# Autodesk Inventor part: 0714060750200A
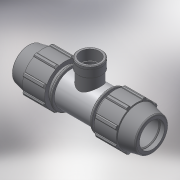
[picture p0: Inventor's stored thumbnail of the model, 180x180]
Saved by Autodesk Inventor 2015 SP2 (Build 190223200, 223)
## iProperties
Created: 2017-02
Part Number: 0714060750200A
Material: Generic
Description: PLASSON TEE WITH THREADED FEMALE OFFTAKE 75-2"-75
Document SubType Name: Modeling
Designer: KIM
Mass: 92.6774 g
Surface Area: 199.44 cm^2
Volume: 66.1981 cm^3
Density: 1 g/cm^3
Appearance: Default
Author: KIM
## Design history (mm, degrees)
derived "87140.ipt"
feature "Solid1::87140.ipt"
feature "Solid2::87140.ipt"
tag "TaggingFeature1"
body "Solid1"
other parameters: "d2" = 75, "d4" = 14.95833, "d5" = 43.08, "d7" = 134, "d11" = 5.98333, "d13" = 120 deg, "d14" = 97.5, "d15" = 12 deg, "d16" = 116.58, "d18" = 3.75, "d19" = 35 deg, "d20" = 17.5 deg, "d21" = 124.62, "d23" = 0, "d25" = 360 deg, "d27" = 2.68, "d33" = 1.5, "d42" = 64.62, "d43" = 4.02, "d46" = 2.25, "d68" = 10.77, "d76" = 56.656, "d80" = 1.69968, "d91" = 100.5, "d93" = 132, "d95" = 67.5, "d115" = 70.82, "d116" = 135 deg, "d117" = 65.1544, "d118" = 359, "d119" = 67.5, "d121" = 0, "d122" = 50.625, "d124" = 0, "d128" = 0, "d129" = 7.5, "d130" = 9, "d131" = 0.3, "d132" = 0.3, "d133" = 70.82, "d_" = 75, "E_" = 134, "l_" = 132, "Rp_" = 56.656, "H_" = 359
